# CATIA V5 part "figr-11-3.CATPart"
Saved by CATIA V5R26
Part number: Part1
Bounding box of the stored display mesh (mm): x -50 to 50, y -98.731 to 72.975, z 0 to 120
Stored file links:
  D:\_Deepak\CATIA\CATIA V5-6R2016_Deepak\Resources\Part files\Partfiles\c11_catia_v5_6r2016_prt\figr-11-3.CATPart
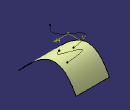
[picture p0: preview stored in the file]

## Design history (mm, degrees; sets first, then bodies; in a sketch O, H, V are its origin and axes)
Set1
  Sketch1 on yz-plane, origin (0, 0, 0), H (0, 1, 0), V (0, 0, 1)
    spline S1 through (-98.7309, 0) (-73.2816, 27.1192) (0, 74.8227) (72.975, 18.624)
    point P1 (-98.7309, 0)
    point P2 (0, 74.8227)
    coincidence: P1 H, P2 V
  Extrude1: Element1 Sketch1, Lim1 50, Lim2 50, Direction yz-plane
  Plane1: type Offset, RefPlane xy-plane, Offset 120
  Sketch2 on Plane1, origin (0, 0, 120), H (1, 0, 0), V (0, 1, 0)
    spline S1 through (28.7787, 44.6229) (-22.3035, 19.7059) (20.5049, -22.8447) (5.396, -48.9118)
  Project1: ToProject Sketch2, Support Extrude1
Body1 (main body)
